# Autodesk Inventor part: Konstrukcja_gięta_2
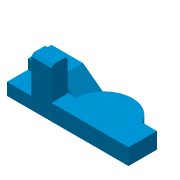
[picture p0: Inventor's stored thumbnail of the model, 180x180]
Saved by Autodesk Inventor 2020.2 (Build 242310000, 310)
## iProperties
Created: 2014-08
Part Number: Konstrukcja_gięta_2
Material: Ogólny
Document SubType Name: Modeling
Designer: F.Stasiak
Density: 1 g/cm^3
Appearance: Domyślna
Catalog Web Link: www.expertbooks.pl
Manager: www.cadconsulting.pl
Company: Fabian Stasiak CAD Consulting
Author: Fabian
Title: C:\Zbiór ćwiczeń AI 2015 III ROBOCZY\Rury\Konstrukcja_gięta_2.stp
Creation Date: 2014-08-25
Sending System: Autodesk Inventor 2015
Preprocessor: ST-DEVELOPER v15.6
Author: F.Stasiak
Subject: Zbiór ćwiczeń. Autodesk Inventor 2020. Kurs Professional
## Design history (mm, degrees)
node "Konstrukcja_gięta_21"
node "Bryła1"
node "Baza1"
